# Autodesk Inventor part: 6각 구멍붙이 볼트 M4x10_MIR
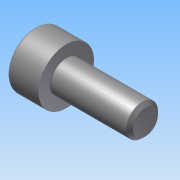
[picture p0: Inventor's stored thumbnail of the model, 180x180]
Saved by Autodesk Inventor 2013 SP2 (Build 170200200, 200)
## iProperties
Created: 2026-07
Part Number: 6각 구멍붙이 볼트 M4x10_MIR
Material: Generic
Document SubType Name: Modeling
Designer: aa
Density: 1 g/cm^3
Author: aa
변환 표준: STEP AP214IS
전처리기: Build: 200, Release: 2013 SP2 Update 6 - Date: Thu 07/17/2014
전송 단위: 밀리미터
불확실성: 0.01
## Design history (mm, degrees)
derived "6각 구멍붙이 볼트 M4x10.ipt"
feature "Solid1::6각 구멍붙이 볼트 M4x10.ipt" dims "d0" = 10
tag "피쳐 태그1"
node "솔리드1"
